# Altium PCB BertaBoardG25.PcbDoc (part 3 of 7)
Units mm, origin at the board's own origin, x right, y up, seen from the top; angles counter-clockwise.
Board outline 160 x 160 mm, 4 copper layers (Top, GND Plane, Power Plane, Bottom), stack 1.344 mm thick; 17 components, 112 nets, 2311 pads, 138 vias.
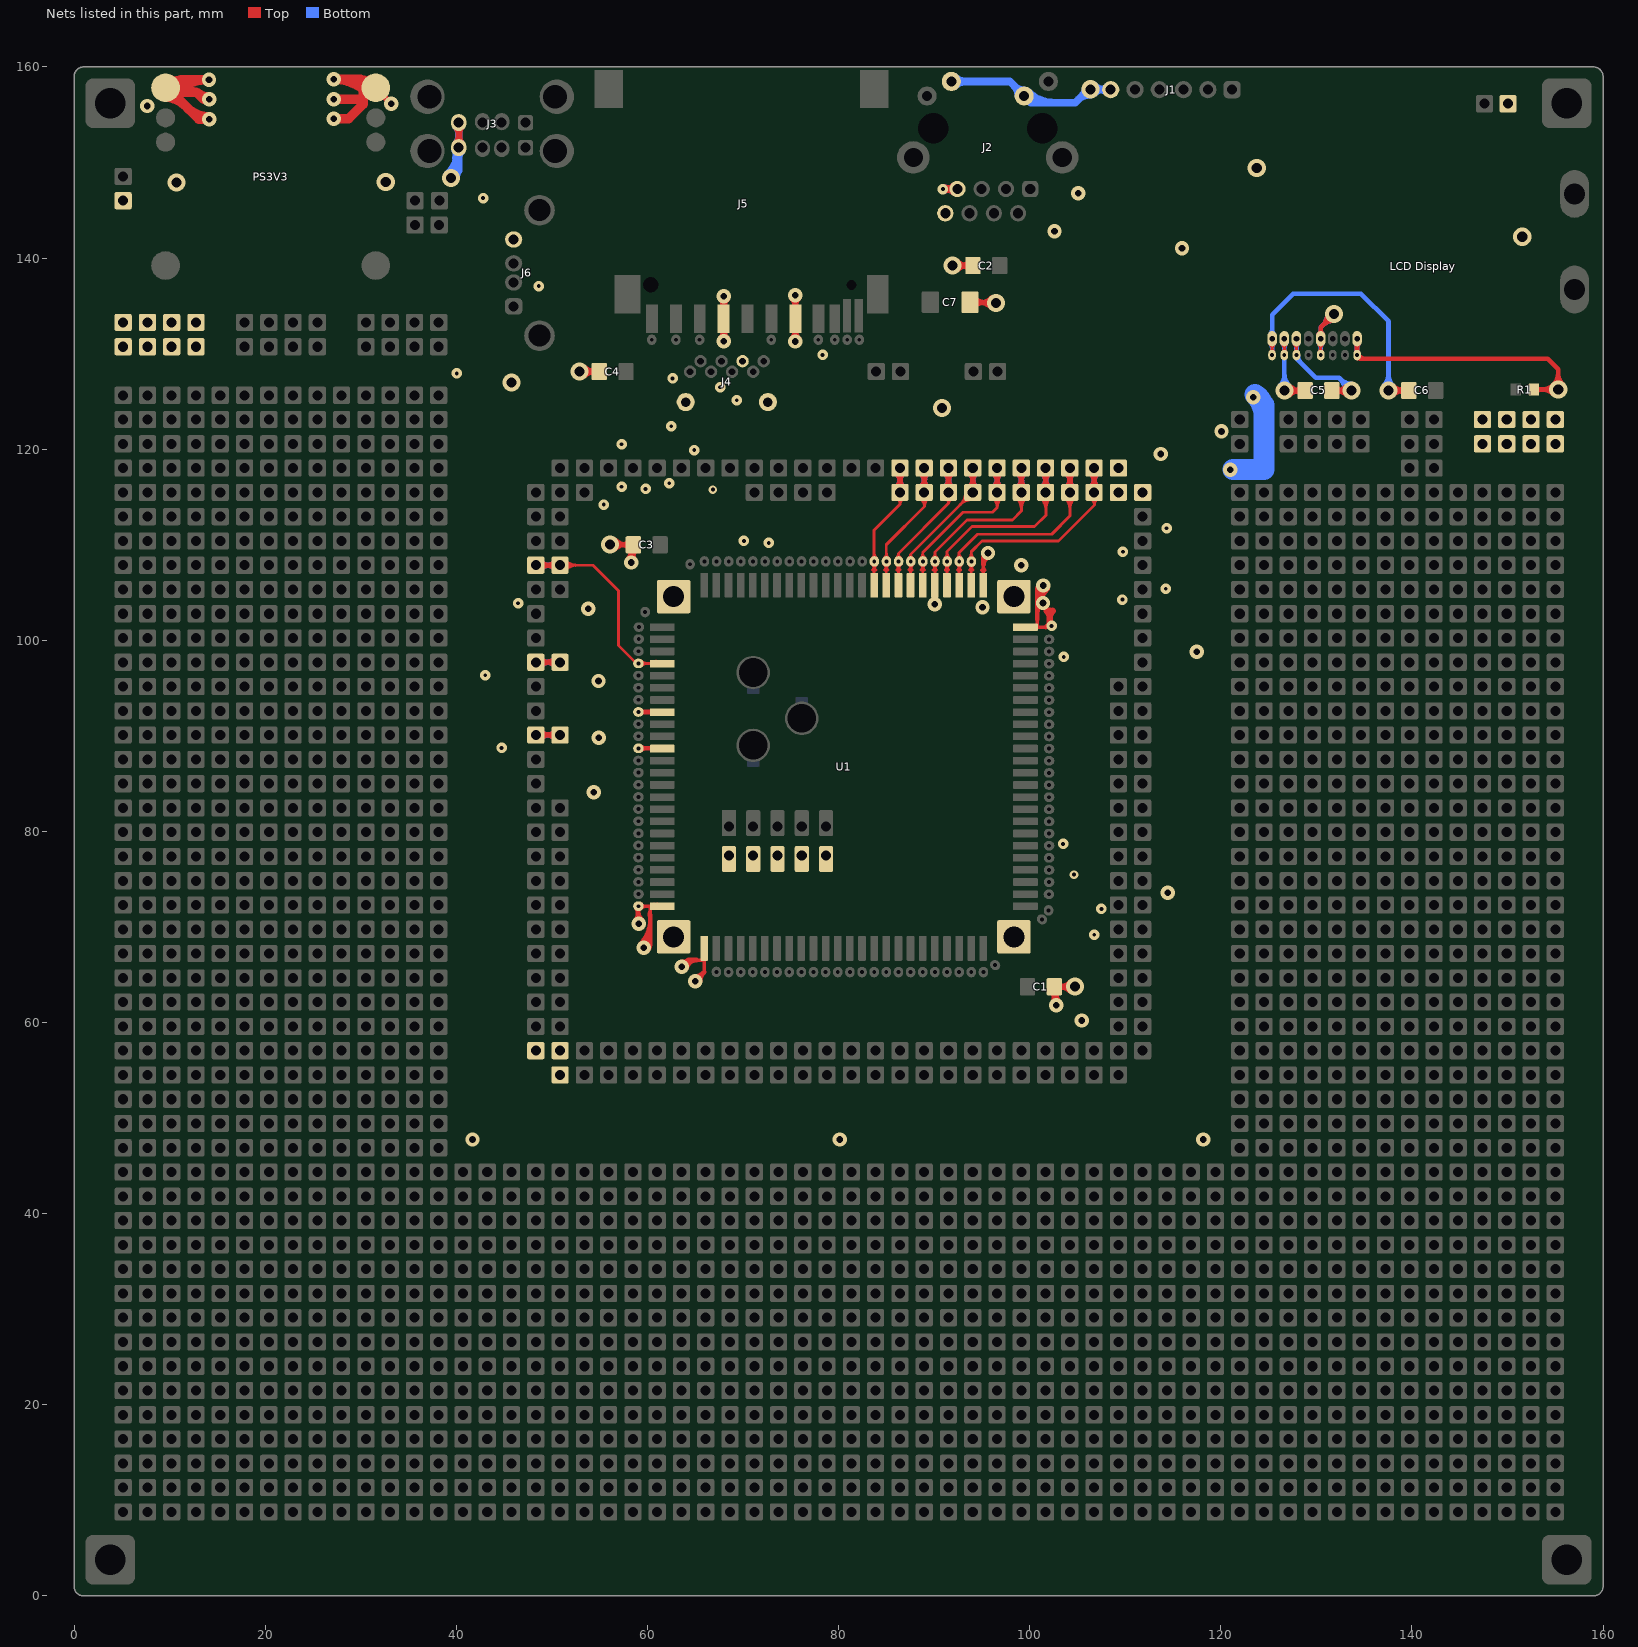
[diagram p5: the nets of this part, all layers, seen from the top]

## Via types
v1: diameter 1.5, hole 0.7, Top to Bottom, tented both sides, 54 vias
v2: diameter 1.1, hole 0.4, Top to Bottom, tented both sides, 49 vias
v3: diameter 1.9, hole 1.05, Top to Bottom, tented both sides, 17 vias
v4: diameter 1.9, hole 1.05, Top to Bottom, 16 vias
v5: diameter 0.9, hole 0.4, Top to Bottom, tented both sides, 2 vias

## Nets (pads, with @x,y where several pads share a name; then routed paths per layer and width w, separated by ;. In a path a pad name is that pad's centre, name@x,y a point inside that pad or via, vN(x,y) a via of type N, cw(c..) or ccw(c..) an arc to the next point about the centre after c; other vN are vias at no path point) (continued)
GND: "LCD Display.5" C1.2 C2.2 C3.2 C4.2 C7.1 J1.6 J2.8 J2.10 J2.11 J3.4 J3.8 J4.6 J4.9 J4.10 J5.3 J5.6 J6.4 pad.0@5.142,130.72 pad.0@5.142,133.26 pad.0@5.142,146 pad.0@7.682,130.72 pad.0@7.682,133.26 pad.0@10.222,130.72 pad.0@10.222,133.26 pad.0@12.762,130.72 pad.0@12.762,133.26 pad.0@48.322,57.06 pad.0@48.322,90.08 pad.0@48.322,97.7 pad.0@50.862,54.52 pad.0@50.862,57.06 pad.0@50.862,90.08 pad.0@50.862,97.7 pad.0@59.06,72.182 pad.0@59.06,88.695 pad.0@59.06,92.502 pad.0@109.282,115.48 pad.0@109.282,118.02 pad.0@111.822,115.48 pad.0@130.454,129.853 pad.0@147.382,120.56 pad.0@147.382,123.1 pad.0@149.922,120.56 pad.0@149.922,123.1 pad.0@150.042,156.15 pad.0@152.462,120.56 pad.0@152.462,123.1 pad.0@155.002,120.56 pad.0@155.002,123.1 PS3V3.1 PS3V3.8 U1.2 U1.10 U1.E1 U1.E14 U1.E17 U1.H1 U1.H2 U1.H3 U1.H4 U1.N24 U1.S24 U1.W1 | length 353.6
  Top w0.3: pad.0@48.331,90.11 pad.0@50.871,90.11 ; pad.0@48.331,97.73 pad.0@50.871,97.73 ; pad.0@48.64,89.761 cw(c49.481,88.92) 49.481,90.11 ; pad.0@48.64,90.398 ccw(c49.335,91.093) 49.335,90.11 ; pad.0@48.64,97.381 cw(c49.481,96.54) 49.481,97.73 ; pad.0@48.64,98.018 ccw(c49.335,98.713) 49.335,97.73 ; pad.0@48.685,90.346 ccw(c49.117,90.663) 49.255,90.145 ; pad.0@48.685,97.966 ccw(c49.117,98.283) 49.255,97.765 ; pad.0@48.852,89.549 cw(c50.205,88.196) pad.0@50.205,90.11 ; pad.0@48.852,90.61 ccw(c50.06,91.817) pad.0@50.06,90.11 ; pad.0@48.852,97.169 cw(c50.205,95.816) pad.0@50.205,97.73 ; pad.0@48.852,98.23 ccw(c50.06,99.437) pad.0@50.06,97.73 ; pad.0@48.927,90.523 ccw(c49.496,90.941) 49.679,90.258 ccw(c49.976,89.15) pad.0@48.976,89.712 ; pad.0@48.927,98.143 ccw(c49.496,98.561) 49.679,97.878 ccw(c49.976,96.77) pad.0@48.976,97.332 ; pad.0@48.961,89.687 cw(c49.453,89.385) 49.602,89.943 cw(c49.859,90.903) pad.0@48.983,90.434 ; pad.0@48.961,97.307 cw(c49.453,97.005) 49.602,97.563 cw(c49.859,98.523) pad.0@48.983,98.054 ; pad.0@48.978,90.11 cw(c48.978,88.196) pad.0@50.331,89.549 ; pad.0@48.978,97.73 cw(c48.978,95.816) pad.0@50.331,97.169 ; pad.0@49.124,90.11 ccw(c49.124,91.817) pad.0@50.331,90.61 ; pad.0@49.124,97.73 ccw(c49.124,99.437) pad.0@50.331,98.23 ; 49.703,90.11 cw(c49.703,88.92) pad.0@50.544,89.761 ; 49.703,97.73 cw(c49.703,96.54) pad.0@50.544,97.381 ; 49.848,90.11 ccw(c49.848,91.093) pad.0@50.544,90.398 ; 49.848,97.73 ccw(c49.848,98.713) pad.0@50.544,98.018 ; 130.206,131.014 cw(c129.609,130.417) 130.454,130.417 cw(c131.299,130.417) 130.701,131.014 ; pad.0@130.277,130.179 ccw(c129.85,130.606) 130.454,130.606 ccw(c131.057,130.606) pad.0@130.631,130.179 ; pad.0@130.454,130.16 130.454,131.562
  Top w0.35: pad.0@59.34,71.952 cw(c59.852,71.44) 59.852,72.165 ; pad.0@59.34,72.412 ccw(c59.937,73.009) 59.937,72.165 ; pad.0@59.427,72.165 U1.E1@61.551,72.165 ; 60.185,71.146 cw(c61.921,71.146) U1.E1@60.694,72.373 ; 60.302,71.256 U1.E1@60.302,72.145 ; U1.E1@60.582,72.093 ccw(c60.582,72.616) U1.E1@61.041,72.365 ; U1.E1@61.2,72.165 ccw(c61.2,72.364) U1.E1@61.375,72.268 ; 65.139,66.54 U1.N24@65.901,66.54 ; U1.N24@65.787,67.211 cw(c65.403,66.827) 65.946,66.827 cw(c66.489,66.826) U1.N24@66.105,67.211 ; 65.946,65.284 U1.N24@65.946,67.77 ; 94.997,107.329 ccw(c94.613,107.713) 95.156,107.713 ccw(c95.699,107.713) 95.315,107.329 ; U1.S24@95.136,105.79 U1.S24@95.156,105.77 95.156,108.01 ; U1.W1@99.551,101.375 101.675,101.375 ; U1.W1@99.728,101.478 ccw(c99.902,101.574) U1.W1@99.902,101.375 ; U1.W1@100.8,101.507 100.8,102.193
  Top w0.4: PS3V3.8@31.579,157.819 PS3V3.8@31.916,157.819
  Top w0.5: v4@52.903,128.122 C4.2@54.959,128.122 ; v4@53.396,127.625 cw(c54.595,126.427) C4.2@54.595,128.122 ; v4@53.396,128.615 ccw(c54.588,129.807) C4.2@54.588,128.122 ; v4@53.533,128.422 ccw(c53.881,128.589) 53.981,128.216 ccw(c54.155,127.569) v4@53.542,127.839 ; v4@53.535,127.824 cw(c53.879,127.663) 53.977,128.029 cw(c54.148,128.669) v4@53.542,128.402 ; C4.2@54.57,127.733 ccw(c53.631,126.794) 53.631,128.122 ccw(c53.631,129.45) C4.2@54.57,128.511 ; v4(56.102,110.04) 56.151,109.99 C3.2@58.302,109.99 ; v4@56.597,109.545 cw(c57.672,108.469) 57.672,109.99 ; v4@56.597,110.535 ccw(c57.911,111.849) C3.2@57.911,109.99 ; v1@57.948,108.493 ccw(c57.095,109.347) 58.302,109.347 ccw(c59.509,109.347) v1@58.655,108.493 ; v1@58.139,108.612 ccw(c57.931,109.219) 58.55,109.053 ccw(c59.18,108.885) v1@58.683,108.463 ; C3.2@58.14,109.501 cw(c57.748,109.11) C3.2@58.302,109.11 ; C3.2@58.14,109.601 ccw(c57.201,108.662) 57.201,109.99 ccw(c57.201,111.318) C3.2@58.14,110.379 ; v1@58.302,108.125 cw(c60.145,108.125) C3.2@58.9,109.485 ; v1(58.302,108.14) C3.2@58.302,109.99 ; C3.2@58.302,109.999 C3.2@58.302,109.99 ; C3.2@58.528,109.99 C3.2@58.302,109.99 ; v1@58.748,70.693 ccw(c58.136,71.305) 59.002,71.305 ; pad.0@58.833,72.005 cw(c58.426,71.599) 59.002,71.599 ; v1@59.002,70.44 pad.0@59.002,71.74 ; 59.002,71.559 cw(c59.633,71.559) pad.0@59.187,72.005 ; pad.0@59.06,88.695 61.531,88.695 U1.E14@61.551,88.675 ; pad.0@59.06,92.502 61.534,92.502 U1.E17@61.551,92.485 ; v1@59.248,68.193 ccw(c56.705,70.737) 60.302,70.737 ; pad.0@59.287,88.518 cw(c59.714,88.091) 59.714,88.695 cw(c59.714,89.298) pad.0@59.287,88.872 ; pad.0@59.287,92.325 cw(c59.714,91.899) 59.714,92.502 cw(c59.714,93.106) pad.0@59.287,92.679 ; pad.0@59.427,72.165 pad.0@59.002,71.74 ; v1@59.447,70.702 cw(c60.435,71.74) pad.0@59.002,71.74 ; v1@59.676,68.334 ccw(c59.786,69.056) 60.302,68.54 ; v1@59.955,67.486 ccw(c59.119,68.322) 60.302,68.322 ; v1@60.096,67.914 cw(c60.818,68.023) 60.302,68.54 ; 60.302,69.53 cw(c57.912,69.53) v1(59.602,67.84) 60.302,68.54 ; 60.302,71.256 60.302,68.54 ; v1@63.676,66.334 ccw(c63.786,67.056) 64.302,66.54 ; v1@64.087,65.718 cw(c65.139,65.455) 65.139,66.54 64.302,66.54 ; v1@64.096,65.914 cw(c64.818,66.023) 64.302,66.54 ; 64.498,66.54 ccw(c64.498,65.615) v1(63.602,65.84) 64.302,66.54 ; v1(65.002,64.34) 65.946,65.284 ; v1@65.002,64.84 ccw(c65.002,66.047) 65.855,65.193 ccw(c66.709,64.34) v1@65.502,64.34 ; v4(91.916,139.213) C2.2@94.058,139.211 ; v4@92.411,138.718 cw(c93.603,137.526) C2.2@93.603,139.211 ; v4@92.411,139.708 ccw(c93.61,140.906) C2.2@93.61,139.211 ; v4@92.538,138.891 cw(c93.246,138.524) 93.04,139.294 cw(c92.929,139.706) v4@92.546,139.519 ; v4@92.538,139.535 ccw(c93.252,139.904) 93.044,139.127 ccw(c92.932,138.708) v4@92.543,138.901 ; C2.2@93.67,138.822 ccw(c92.731,137.883) 92.731,139.211 ccw(c92.731,140.539) C2.2@93.67,139.6 ; C7.1@93.754,135.183 93.901,135.33 96.391,135.33 v4@96.461,135.26 ; C7.1@94.213,134.923 cw(c95.195,133.941) 95.195,135.33 ; C7.1@94.213,135.842 ccw(c95.451,137.079) 95.451,135.33 ; 94.734,135.33 cw(c94.734,133.587) v4@95.966,134.819 ; 94.809,135.33 ccw(c94.809,136.967) v4@95.966,135.809 ; 95.156,107.912 cw(c95.957,107.912) v1@95.764,108.689 ; 95.156,108.01 95.156,108.687 95.643,109.174 ccw(c95.798,108.551) 95.156,108.551 ; 100.801,102.193 100.801,105 ; 100.801,102.803 cw(c104.398,102.803) v1@101.854,105.346 ; v1@100.801,104.01 cw(c103.191,104.01) v1@101.501,105.7 ; 100.801,105.217 cw(c101.983,105.217) v1@101.147,106.053 ; v1@101.006,105.625 cw(c100.284,105.516) 100.801,105 ; v1@101.426,105.205 ccw(c101.317,104.484) 100.801,105 ; v1(101.43,105.734) 101.467,105.734 v1@101.501,105.7 ; 101.675,101.375 v2@102.101,101.8 ; 102.001,103.2 102.101,103.1 ; C1.2@102.185,63.26 cw(c100.698,61.774) v1@102.801,61.774 ; v1@102.388,61.983 ccw(c101.579,62.539) 102.528,62.793 ccw(c103.551,63.067) v1@103.041,62.138 ; v1@102.447,62.053 ccw(c101.593,62.907) 102.801,62.907 ccw(c104.008,62.907) v1@103.154,62.053 ; C1.2@102.574,63.749 C1.2@102.801,63.749 ; v1@102.801,61.7 C1.2@102.801,63.749 ; C1.2@102.801,62.869 cw(c103.354,62.869) C1.2@102.963,63.26 ; C1.2@102.963,63.36 cw(c103.902,62.422) 103.902,63.749 cw(c103.902,65.077) C1.2@102.963,64.138 ; C1.2@103.016,63.749 ccw(c103.016,65.475) v4@104.236,64.255 ; C1.2@103.066,63.749 cw(c103.066,62.095) v4@104.236,63.265 ; v4@104.095,64.052 cw(c103.72,64.225) 103.614,63.826 cw(c103.406,63.051) v4@104.114,63.43 ; v4@104.113,64.087 cw(c103.36,64.486) 103.58,63.663 cw(c103.701,63.213) v4@104.113,63.431 ; v4@104.96,63.161 104.372,63.749 C1.2@102.801,63.749 ; 130.277,132.039 ccw(c129.85,132.466) 130.454,132.466 ccw(c131.057,132.466) 130.631,132.039 ; 130.454,131.562 130.454,132.752 v3(131.861,134.16) v3@132.061,134.16 ; v3@131.161,134.16 cw(c129.471,134.16) 130.666,132.965 cw(c131.861,131.77) v3@131.861,133.46 ; 100.801,105 v1@101.501,105.7
  Top w0.6: PS3V3.8@31.687,157.641 v1(33.186,156.143) v1@33.287,156.041
  Top w0.7: J3.4@39.934,151.971 ccw(c39.103,152.802) 40.278,152.802 ; J3.8@39.934,153.755 cw(c39.103,152.924) 40.278,152.924 ; J3.4@40.278,151.553 J3.8@40.278,154.173 ; 40.278,152.676 ccw(c41.276,152.676) J3.4@40.57,151.971 ; 40.278,153.049 cw(c41.276,153.049) J3.8@40.57,153.755 ; v1@67.718,131.583 ccw(c67.035,132.266) 68.001,132.266 ccw(c68.966,132.266) v1@68.283,131.583 ; v1@67.718,135.717 cw(c67.035,135.034) 68.001,135.034 cw(c68.966,135.034) v1@68.283,135.717 ; J5.3@67.783,132.583 cw(c67.257,132.057) 68.001,132.057 ; J5.3@67.783,134.722 ccw(c67.257,135.248) 68.001,135.248 ; v1(68.001,131.3) v1(68.001,136) ; v1@75.188,135.817 cw(c74.505,135.134) 75.471,135.134 cw(c76.436,135.134) v1@75.753,135.817 ; v1@75.198,131.543 ccw(c74.539,132.201) J5.6@75.471,132.201 ; J5.6@75.283,132.583 cw(c74.829,132.13) 75.471,132.13 ; J5.6@75.283,134.722 ccw(c74.829,135.176) 75.471,135.176 ; v1@75.471,131.34 v1@75.471,136.04 ; 75.471,132.098 cw(c76.157,132.098) J5.6@75.672,132.583 ; J5.6@75.471,132.25 ccw(c76.47,132.25) v1@75.763,131.543 ; 75.471,135.207 ccw(c76.157,135.207) J5.6@75.672,134.722 ; 101.818,103.077 cw(c101.135,102.394) 102.101,102.394 cw(c103.066,102.394) 102.383,103.077 ; v2@102.101,101.8 102.101,103.1
  Top w1: PS3V3.1@9.579,156.819 cw(c9.579,153.962) 11.599,155.982 ; PS3V3.1@9.579,157.819 cw(c11.589,155.809) 11.589,158.651 ; PS3V3.1@9.761,157.82 13.06,154.521 v1(14.143,154.521) ; PS3V3.1@10.206,158.598 ccw(c10.669,159.174) 11.192,158.651 ; PS3V3.1@10.286,157.111 cw(c14.003,153.395) v1@14.003,158.651 ; PS3V3.1@10.326,158.484 ccw(c12.811,160.699) 12.811,157.37 ; PS3V3.1@10.579,157.819 ccw(c12.551,157.819) 11.157,156.424 ; 11.867,155.714 ccw(c14.143,157.99) v1@14.143,154.771 ; v1@14.128,156.87 cw(c14.024,158.583) 12.811,157.37 ; v1(14.133,158.651) 11.192,158.651 ; v1(14.143,156.621) 13.56,156.621 12.811,157.37 ; v1(27.179,156.619) 29.662,156.619 ; v1(27.19,154.588) 28.749,154.588 30.261,156.101 30.261,158.46 30.002,158.719 ; 29.495,158.719 cw(c29.495,155.856) PS3V3.8@31.579,157.819 ; PS3V3.8@30.851,157.133 ccw(c27.179,153.674) 27.179,158.719 30.002,158.719 ; PS3V3.8@31,158.634 cw(c30.551,159.268) 30.002,158.719 ; 11.192,158.651 11.011,158.47 11.011,157.37 12.811,157.37
  Bottom w0.3: pad.0@48.331,90.11 pad.0@50.871,90.11 ; pad.0@48.331,97.73 pad.0@50.871,97.73 ; pad.0@48.64,89.761 cw(c49.481,88.92) 49.481,90.11 ; pad.0@48.64,90.398 ccw(c49.335,91.093) 49.335,90.11 ; pad.0@48.64,97.381 cw(c49.481,96.54) 49.481,97.73 ; pad.0@48.64,98.018 ccw(c49.335,98.713) 49.335,97.73 ; pad.0@48.685,90.346 ccw(c49.117,90.663) 49.255,90.145 ; pad.0@48.685,97.966 ccw(c49.117,98.283) 49.255,97.765 ; pad.0@48.852,89.549 cw(c50.205,88.196) pad.0@50.205,90.11 ; pad.0@48.852,90.61 ccw(c50.06,91.817) pad.0@50.06,90.11 ; pad.0@48.852,97.169 cw(c50.205,95.816) pad.0@50.205,97.73 ; pad.0@48.852,98.23 ccw(c50.06,99.437) pad.0@50.06,97.73 ; pad.0@48.927,90.523 ccw(c49.496,90.941) 49.679,90.258 ccw(c49.976,89.15) pad.0@48.976,89.712 ; pad.0@48.927,98.143 ccw(c49.496,98.561) 49.679,97.878 ccw(c49.976,96.77) pad.0@48.976,97.332 ; pad.0@48.961,89.687 cw(c49.453,89.385) 49.602,89.943 cw(c49.859,90.903) pad.0@48.983,90.434 ; pad.0@48.961,97.307 cw(c49.453,97.005) 49.602,97.563 cw(c49.859,98.523) pad.0@48.983,98.054 ; pad.0@48.978,90.11 cw(c48.978,88.196) pad.0@50.331,89.549 ; pad.0@48.978,97.73 cw(c48.978,95.816) pad.0@50.331,97.169 ; pad.0@49.124,90.11 ccw(c49.124,91.817) pad.0@50.331,90.61 ; pad.0@49.124,97.73 ccw(c49.124,99.437) pad.0@50.331,98.23 ; 49.703,90.11 cw(c49.703,88.92) pad.0@50.544,89.761 ; 49.703,97.73 cw(c49.703,96.54) pad.0@50.544,97.381 ; 49.848,90.11 ccw(c49.848,91.093) pad.0@50.544,90.398 ; 49.848,97.73 ccw(c49.848,98.713) pad.0@50.544,98.018
  Bottom w0.5: 130.277,131.085 cw(c129.85,130.658) 130.454,130.658 cw(c131.057,130.658) 130.631,131.085 ; 130.277,132.039 ccw(c129.85,132.466) 130.454,132.466 ccw(c131.057,132.466) 130.631,132.039 ; pad.0@130.461,130.16 130.454,130.167 130.454,131.562 130.454,132.752 v3(131.861,134.16) v3@132.061,134.16 ; v3@131.161,134.16 cw(c129.471,134.16) 130.666,132.965 cw(c131.861,131.77) v3@131.861,133.46
  Bottom w0.8: v3@39.076,148.752 ccw(c36.331,151.553) J3.4@40.252,151.553 ; v3(39.461,148.36) 40.252,149.151 J3.4@40.252,151.553 ; v3@39.636,148.181 ccw(c38.198,149.648) 40.252,149.648 ; J3.4@39.906,151.253 cw(c39.146,150.814) 39.993,150.587 ; 39.961,150.466 cw(c40.979,150.194) J3.4@40.452,151.106 ; J3.8@40.252,154.173 J3.4@40.252,151.553 ; J2.11@91.804,158.478 97.904,158.478 J2.10@99.424,156.958 100.122,156.26 104.761,156.26 106.111,157.61 108.09,157.61 J1.6@108.48,157.22 ; J2.11@92.228,158.053 cw(c93.253,157.029) 93.253,158.478 cw(c93.253,159.926) J2.11@92.228,158.902 ; J2.10@98.824,156.958 ccw(c97.376,156.958) 98.4,157.982 ccw(c99.424,159.006) J2.10@99.424,157.558 ; J2.10@99.283,156.816 ccw(c100.626,158.16) 100.626,156.26 ; J2.10@99.848,157.382 ccw(c102.558,160.091) 102.558,156.26 ; 105.081,156.579 cw(c106.361,155.299) v3@106.361,157.11 ; 105.564,157.062 ccw(c104.966,157.66) v3@105.811,157.66 ; v3@106.75,157.271 cw(c107.568,156.453) 107.568,157.61 ; v3@106.75,158.049 ccw(c107.81,159.108) J1.6@107.81,157.61 ; 107.369,157.61 ccw(c107.369,158.731) J1.6@108.162,157.938 ; 107.418,157.61 cw(c107.418,156.558) J1.6@108.162,157.302 ; 40.252,150.487 cw(c41.218,150.487) 40.535,151.17 ccw(c41.218,150.487) 40.252,150.487 ; 40.252,150.487 ccw(c39.286,150.487) 39.969,151.17 cw(c39.286,150.487) 40.252,150.487 ; 40.252,152.618 cw(c39.286,152.618) 39.969,151.936 ccw(c39.286,152.618) 40.252,152.618 ; 40.252,152.618 ccw(c41.218,152.618) 40.535,151.936 cw(c41.218,152.618) 40.252,152.618 ; 40.252,153.107 cw(c41.218,153.107) 40.535,153.79 ccw(c41.218,153.107) 40.252,153.107 ; 40.252,153.107 ccw(c39.286,153.107) 39.969,153.79 cw(c39.286,153.107) 40.252,153.107
  Bottom w2.2: v1@121.281,117.86 124.511,117.86 124.511,124.62 ; v1@123.562,125.719 cw(c122.542,124.035) 124.511,124.035 ; v1@123.629,125.667 cw(c121.498,123.537) 124.511,123.537
  other v1: 41.701,47.77 80.125,47.77 118.171,47.77 105.461,60.22 102.765,61.818 59.102,70.34 114.461,73.58 54.4,84.1 54.9,89.8 54.877,95.741 117.481,98.82 53.801,103.3 95.07,103.469 90.052,103.764 101.4,103.9 99.122,107.839 95.646,109.138 121.001,117.85 113.701,119.5 120.071,121.86 123.381,125.42 75.481,131.26 75.471,136.1 115.931,141.02 102.601,142.8 105.073,146.79 7.659,155.914 27.179,158.719
  other v2: 106.751,69.2 107.501,71.9 103.501,78.7 44.74,88.733 43.039,96.353 103.561,98.26 102.3,101.5 46.468,103.872 109.701,104.26 114.241,105.4 109.761,109.26 72.701,110.2 70.101,110.4 114.331,111.73 55.431,114.2 59.801,115.84 57.301,116.07 62.294,116.442 64.901,119.9 57.301,120.51 62.501,122.4 69.355,125.129 67.603,126.475 62.641,127.41 40.041,127.926 78.331,129.86 48.627,137.07 42.809,146.272
  other v3: 90.821,124.31 45.791,126.98 151.541,142.23 10.735,147.906 32.621,147.95 123.761,149.44 106.361,157.66
  other v4: 104.731,63.76 52.901,128.12 96.461,135.314
  other v5: 104.639,75.486 66.851,115.774
JTAGSEL: U1.4
NetC5_1: "LCD Display.2" C5.1 pad.0@126.644,129.853 | length 22.1
  Top w0.3: 126.396,131.014 cw(c125.799,130.417) 126.644,130.417 cw(c127.489,130.417) 126.891,131.014 ; pad.0@126.467,130.179 ccw(c126.04,130.606) 126.644,130.606 ccw(c127.247,130.606) pad.0@126.821,130.179 ; pad.0@126.644,130.16 126.644,131.562
  Top w0.5: v4@126.682,126.116 C5.1@128.822,126.116 ; v4@127.175,125.649 cw(c128.302,124.523) C5.1@128.302,126.116 ; v4@127.175,126.639 ccw(c128.439,127.903) C5.1@128.439,126.116 ; v4@127.293,125.806 cw(c127.717,125.572) 127.843,126.04 cw(c128.068,126.883) v4@127.298,126.473 ; v4@127.306,125.83 cw(c127.958,125.501) 127.769,126.207 cw(c127.671,126.574) v4@127.323,126.423 ; v4@127.429,126.116 ccw(c127.429,127.536) C5.1@128.433,126.532 ; v4@127.56,126.116 cw(c127.56,124.88) C5.1@128.433,125.754
  Bottom w0.5: v4@126.185,126.639 ccw(c125.078,127.746) 126.644,127.746 ; 126.467,131.085 cw(c126.04,130.658) 126.644,130.658 cw(c127.247,130.658) 126.821,131.085 ; v4@126.644,126.16 pad.0@126.644,129.853 126.644,131.562 ; 126.644,127.923 ccw(c128.458,127.923) v4@127.175,126.639
  other v4: 126.68,126.144
NetC5_2: "LCD Display.3" C5.2 pad.0@127.913,129.853 | length 26.3
  Top w0.3: 127.665,131.014 cw(c127.068,130.416) 127.913,130.416 cw(c128.758,130.416) 128.16,131.014 ; pad.0@127.736,130.179 ccw(c127.309,130.606) 127.913,130.606 ccw(c128.516,130.606) pad.0@128.09,130.179 ; pad.0@127.913,130.16 127.913,131.561
  Top w0.5: C5.2@131.622,126.116 v4@133.679,126.116 ; C5.2@131.922,126.116 ccw(c131.922,127.903) v4@133.185,126.639 ; C5.2@132.011,125.754 cw(c132.885,124.88) v4@132.885,126.116 ; C5.2@132.011,126.532 ccw(c133.015,127.536) v4@133.015,126.116 ; C5.2@132.059,126.116 cw(c132.059,124.523) v4@133.185,125.649 ; v4@133.033,126.411 cw(c132.725,126.538) 132.639,126.217 cw(c132.484,125.639) v4@133.036,125.872 ; v4@133.043,126.435 cw(c132.376,126.739) 132.566,126.03 cw(c132.678,125.61) v4@133.063,125.815
  Bottom w0.5: 127.736,131.085 cw(c127.309,130.658) 127.913,130.658 cw(c128.516,130.658) 128.09,131.085 ; 127.913,131.561 pad.0@127.913,129.853 127.913,129.508 129.947,127.474 132.377,127.474 v4@133.741,126.11 ; pad.0@128.063,129.703 ccw(c128.895,129.703) 128.306,129.114 ; 132.467,127.384 cw(c131.227,126.144) v4@132.98,126.144 ; 132.53,127.321 ccw(c133.68,128.471) v4@133.68,126.844
  other v4: 133.68,126.144
NetC6_1: "LCD Display.1" C6.1 pad.0@125.361,129.853 | length 42.9
  Top w0.3: 125.125,131.014 cw(c124.528,130.416) 125.373,130.416 cw(c126.218,130.416) 125.62,131.014 ; pad.0@125.184,130.179 ccw(c124.729,130.634) 125.373,130.634 ; pad.0@125.373,130.16 125.373,131.561 ; 125.373,130.578 ccw(c125.937,130.578) pad.0@125.538,130.179
  Top w0.5: v4(137.537,126.144) C6.1@139.679,126.143 ; v4@138.032,125.649 cw(c139.224,124.458) C6.1@139.224,126.143 ; v4@138.032,126.639 ccw(c139.231,127.838) C6.1@139.231,126.143 ; v4@138.159,125.822 cw(c138.867,125.455) 138.66,126.226 cw(c138.55,126.638) v4@138.167,126.451 ; v4@138.159,126.466 ccw(c138.873,126.836) 138.665,126.059 ccw(c138.553,125.64) v4@138.164,125.833 ; C6.1@139.29,125.754 ccw(c138.352,124.815) 138.352,126.143 ccw(c138.352,127.471) C6.1@139.29,126.532
  Bottom w0.5: 125.196,131.085 cw(c124.769,130.658) 125.373,130.658 cw(c125.976,130.658) 125.55,131.085 ; 125.196,132.038 ccw(c124.769,132.465) 125.373,132.465 ccw(c125.976,132.465) 125.55,132.038 ; pad.0@125.361,130.16 125.373,130.171 125.373,131.561 125.373,134.071 127.561,136.26 134.661,136.26 137.551,133.37 v4@137.551,126.264 ; v4@137.042,126.639 ccw(c135.814,127.868) 137.551,127.868 ; 137.551,127.801 ccw(c139.194,127.801) v4@138.032,126.639
"NetLCD Display_8": "LCD Display.8" pad.0@134.263,129.853 R1.1 | length 38.6
  Top w0.5: 134.086,131.085 cw(c133.659,130.658) 134.263,130.658 cw(c134.866,130.658) 134.44,131.085 ; 134.263,131.561 pad.0@134.263,129.853 134.263,129.789 134.592,129.46 ; pad.0@134.289,129.555 cw(c134.349,129.217) 134.592,129.46 ; pad.0@134.369,129.809 ccw(c135.212,130.651) 135.212,129.46 ; R1.1@152.981,126.031 cw(c153.486,125.527) 153.486,126.24 ; R1.1@152.981,126.455 ccw(c153.501,126.975) 153.501,126.24 ; R1.1@153.251,126.24 155.301,126.24 155.301,128.35 154.191,129.46 134.592,129.46 ; 153.608,126.24 ccw(c153.608,127.946) 154.814,126.739 ccw(c153.638,127.915) 155.301,127.915 ; 153.63,126.24 cw(c153.63,124.566) v4@154.814,125.749 ; 155.301,127.953 ccw(c157.018,127.953) v4@155.804,126.739
  Bottom w0.5: 134.086,131.085 cw(c133.659,130.658) 134.263,130.658 cw(c134.866,130.658) 134.44,131.085 ; pad.0@134.261,130.16 134.263,130.161 134.263,131.561
  other v4: 155.309,126.244
"NO NET 1": J2.7 | length 14.4
  Top w0.5: v2(90.921,147.22) 92.431,147.22 J2.7@92.439,147.228 ; v2@90.972,147.22 ccw(c90.972,148.695) J2.7@92.015,147.652 ; v2@91.01,147.22 cw(c91.01,145.798) J2.7@92.015,146.803 ; v2@91.071,146.96 cw(c91.472,146.265) J2.7@91.68,147.04 ; v2@91.071,147.48 ccw(c91.455,148.146) J2.7@91.654,147.403 ; v2@91.133,147.008 cw(c91.645,146.496) 91.645,147.22 cw(c91.645,147.944) v2@91.133,147.432 ; v2@91.18,147.07 cw(c91.769,146.73) 91.593,147.386 ; v2@91.18,147.37 ccw(c91.739,147.693) 91.572,147.069
  Bottom w0.5: v2(90.921,147.22) J2.7@92.431,147.22 ; v2@90.972,147.22 ccw(c90.972,148.695) J2.7@92.015,147.652 ; v2@91.01,147.22 cw(c91.01,145.798) J2.7@92.015,146.803 ; v2@91.071,146.96 cw(c91.472,146.265) J2.7@91.68,147.04 ; v2@91.071,147.48 ccw(c91.455,148.146) J2.7@91.654,147.403 ; v2@91.133,147.008 cw(c91.645,146.496) 91.645,147.22 cw(c91.645,147.944) v2@91.133,147.432 ; v2@91.18,147.07 cw(c91.769,146.73) 91.593,147.386 ; v2@91.18,147.37 ccw(c91.739,147.693) 91.572,147.069
NRST: pad.0@48.322,107.86 pad.0@50.862,107.86 pad.0@59.06,97.582 U1.E21 | length 57.4
  Top w0.3: pad.0@48.322,107.86 pad.0@50.862,107.86 54.29,107.86 56.961,105.189 56.961,99.46 58.856,97.565 U1.E21@61.551,97.565 ; pad.0@48.64,107.541 cw(c49.408,106.773) 49.408,107.86 cw(c49.408,108.946) pad.0@48.64,108.178 ; pad.0@48.852,107.329 cw(c50.132,106.049) 50.132,107.86 cw(c50.132,109.67) pad.0@48.852,108.39 ; 49.949,107.81 cw(c50.077,107.331) pad.0@50.488,107.608 ; 49.949,107.909 ccw(c50.077,108.388) pad.0@50.488,108.111 ; pad.0@50.204,107.499 ccw(c49.266,106.983) 49.543,108.018 ccw(c49.709,108.636) pad.0@50.24,108.278 ; pad.0@50.204,108.221 cw(c49.266,108.736) 49.543,107.702 cw(c49.709,107.083) pad.0@50.24,107.441 ; pad.0@50.331,107.329 ccw(c49.051,106.049) 49.051,107.86 ccw(c49.051,109.67) pad.0@50.331,108.39 ; pad.0@50.544,107.541 ccw(c49.775,106.773) 49.775,107.86 ccw(c49.775,108.946) pad.0@50.544,108.178 ; pad.0@51.18,107.541 cw(c51.948,106.773) 51.948,107.86 cw(c51.948,108.946) pad.0@51.18,108.178 ; pad.0@51.392,107.329 cw(c52.672,106.049) 52.672,107.86 cw(c52.672,109.67) pad.0@51.392,108.39 ; pad.0@59.357,97.335 cw(c59.913,96.779) 59.913,97.565 ; pad.0@59.357,97.83 ccw(c59.997,98.469) 59.997,97.565 ; U1.E21@60.292,97.565 ccw(c60.292,98.419) U1.E21@60.9,97.819 ; U1.E21@61.01,97.565 ccw(c61.01,97.71) U1.E21@61.114,97.608
  Bottom w0.3: pad.0@48.322,107.86 pad.0@50.862,107.86 ; pad.0@48.64,107.541 cw(c49.408,106.773) 49.408,107.86 cw(c49.408,108.946) pad.0@48.64,108.178 ; pad.0@48.852,107.329 cw(c50.132,106.049) 50.132,107.86 cw(c50.132,109.67) pad.0@48.852,108.39 ; 49.949,107.81 cw(c50.077,107.331) pad.0@50.488,107.608 ; 49.949,107.909 ccw(c50.077,108.388) pad.0@50.488,108.111 ; pad.0@50.204,107.499 ccw(c49.266,106.983) 49.543,108.018 ccw(c49.709,108.636) pad.0@50.24,108.278 ; pad.0@50.204,108.221 cw(c49.266,108.736) 49.543,107.702 cw(c49.709,107.083) pad.0@50.24,107.441 ; pad.0@50.331,107.329 ccw(c49.051,106.049) 49.051,107.86 ccw(c49.051,109.67) pad.0@50.331,108.39 ; pad.0@50.544,107.541 ccw(c49.775,106.773) 49.775,107.86 ccw(c49.775,108.946) pad.0@50.544,108.178
NRST1: U1.6
NTRST: U1.8
PA0: pad.0@93.904,108.236 pad.0@106.742,115.48 pad.0@106.742,118.02 U1.S23 | length 56.2
  Top w0.3: pad.0@93.656,107.938 cw(c93.101,107.383) 93.886,107.383 ; pad.0@93.656,108.533 ccw(c93.101,109.089) 93.886,109.089 ; 93.709,107.347 ccw(c93.283,107.773) 93.886,107.773 ccw(c94.49,107.773) 94.063,107.347 ; U1.S23@93.886,105.77 93.886,109.265 95.021,110.4 103.001,110.4 106.771,114.17 ; 93.886,107.299 cw(c94.791,107.299) pad.0@94.151,107.938 ; 93.886,109.173 ccw(c94.791,109.173) pad.0@94.151,108.533 ; pad.0@106.211,116.01 ccw(c104.86,117.361) pad.0@106.771,117.361 ; pad.0@106.211,117.489 cw(c104.86,116.138) pad.0@106.771,116.138 ; pad.0@106.349,116.118 ccw(c106.045,116.611) 106.604,116.761 ccw(c107.566,117.019) pad.0@107.096,116.141 ; pad.0@106.374,116.134 ccw(c105.813,117.133) 106.92,116.836 ccw(c107.601,116.654) pad.0@107.185,116.085 ; pad.0@106.384,114.82 cw(c106.031,114.17) 106.771,114.17 ; pad.0@106.424,115.798 ccw(c105.584,116.637) 106.771,116.637 ; pad.0@106.424,117.701 cw(c105.584,116.862) 106.771,116.862 ; pad.0@106.771,116.28 cw(c108.481,116.28) pad.0@107.272,117.489 ; 106.771,116.495 ccw(c107.757,116.495) pad.0@107.06,115.798 ; 106.771,117.004 cw(c107.757,117.004) pad.0@107.06,117.701 ; pad.0@106.771,117.219 ccw(c108.481,117.219) pad.0@107.272,116.01 ; pad.0@106.771,118.06 106.771,114.17 ; 106.807,116.413 ccw(c107.323,116.274) pad.0@107.007,115.843 ; pad.0@107.143,114.846 ccw(c107.571,114.17) 106.771,114.17
  Bottom w0.3: pad.0@106.211,116.01 ccw(c104.86,117.361) pad.0@106.771,117.361 ; pad.0@106.211,117.489 cw(c104.86,116.138) pad.0@106.771,116.138 ; pad.0@106.349,116.118 ccw(c106.045,116.611) 106.604,116.761 ccw(c107.566,117.019) pad.0@107.096,116.141 ; pad.0@106.374,116.134 ccw(c105.813,117.133) 106.92,116.836 ccw(c107.601,116.654) pad.0@107.185,116.085 ; pad.0@106.424,115.798 ccw(c105.584,116.637) 106.771,116.637 ; pad.0@106.424,117.701 cw(c105.584,116.862) 106.771,116.862 ; pad.0@106.771,115.52 pad.0@106.771,118.06 ; pad.0@106.771,116.28 cw(c108.481,116.28) pad.0@107.272,117.489 ; 106.771,116.495 ccw(c107.757,116.495) pad.0@107.06,115.798 ; 106.771,117.004 cw(c107.757,117.004) pad.0@107.06,117.701 ; pad.0@106.771,117.219 ccw(c108.481,117.219) pad.0@107.272,116.01 ; 106.807,116.413 ccw(c107.323,116.274) pad.0@107.007,115.843
PA1: pad.0@92.634,108.261 pad.0@104.202,115.48 pad.0@104.202,118.02 U1.S22 | length 58.4
  Top w0.3: pad.0@92.386,107.963 cw(c91.831,107.408) 92.616,107.408 ; pad.0@92.386,108.558 ccw(c91.831,109.114) 92.616,109.114 ; 92.439,107.347 ccw(c92.013,107.773) 92.616,107.773 ccw(c93.22,107.773) 92.793,107.347 ; U1.S22@92.616,105.77 92.616,109.165 ; 92.616,107.324 cw(c93.521,107.324) pad.0@92.881,107.963 ; pad.0@92.874,108.565 cw(c93.442,109.165) 92.616,109.165 ; pad.0@103.671,114.949 cw(c102.32,113.598) 104.231,113.598 ; pad.0@103.671,116.01 ccw(c102.32,117.361) pad.0@104.231,117.361 ; pad.0@103.671,117.489 cw(c102.32,116.138) pad.0@104.231,116.138 ; pad.0@103.809,117.381 cw(c103.505,116.888) 104.064,116.738 cw(c105.026,116.481) pad.0@104.556,117.358 ; pad.0@103.834,117.366 cw(c103.273,116.367) 104.38,116.663 cw(c105.061,116.846) pad.0@104.645,117.414 ; pad.0@103.884,115.161 cw(c103.044,114.322) 104.231,114.322 ; pad.0@103.884,115.798 ccw(c103.044,116.637) 104.231,116.637 ; pad.0@103.884,117.701 cw(c103.044,116.862) 104.231,116.862 ; 104.231,113.74 cw(c105.941,113.74) pad.0@104.732,114.949 ; 104.231,114.464 cw(c105.217,114.464) pad.0@104.52,115.161 ; pad.0@104.231,116.28 cw(c105.941,116.28) pad.0@104.732,117.489 ; 104.231,116.495 ccw(c105.217,116.495) pad.0@104.52,115.798 ; 104.231,117.004 cw(c105.217,117.004) pad.0@104.52,117.701 ; pad.0@104.231,117.219 ccw(c105.941,117.219) pad.0@104.732,116.01 ; pad.0@104.231,118.06 104.231,113.03 102.301,111.1 94.551,111.1 92.616,109.165 ; 104.267,117.086 cw(c104.783,117.225) pad.0@104.467,117.656
  Bottom w0.3: pad.0@103.671,116.01 ccw(c102.32,117.361) pad.0@104.231,117.361 ; pad.0@103.671,117.489 cw(c102.32,116.138) pad.0@104.231,116.138 ; pad.0@103.809,117.381 cw(c103.505,116.888) 104.064,116.738 cw(c105.026,116.481) pad.0@104.556,117.358 ; pad.0@103.834,117.366 cw(c103.273,116.367) 104.38,116.663 cw(c105.061,116.846) pad.0@104.645,117.414 ; pad.0@103.884,115.798 ccw(c103.044,116.637) 104.231,116.637 ; pad.0@103.884,117.701 cw(c103.044,116.862) 104.231,116.862 ; pad.0@104.231,115.52 pad.0@104.231,118.06 ; pad.0@104.231,116.28 cw(c105.941,116.28) pad.0@104.732,117.489 ; 104.231,116.495 ccw(c105.217,116.495) pad.0@104.52,115.798 ; 104.231,117.004 cw(c105.217,117.004) pad.0@104.52,117.701 ; pad.0@104.231,117.219 ccw(c105.941,117.219) pad.0@104.732,116.01 ; 104.267,117.086 cw(c104.783,117.225) pad.0@104.467,117.656
PA2: pad.0@91.364,108.261 pad.0@101.662,115.48 pad.0@101.662,118.02 U1.S21 | length 57.2
  Top w0.3: pad.0@91.116,107.963 cw(c90.561,107.408) 91.346,107.408 ; pad.0@91.116,108.558 ccw(c90.561,109.114) 91.346,109.114 ; 91.169,107.347 ccw(c90.743,107.773) 91.346,107.773 ccw(c91.95,107.773) 91.523,107.347 ; U1.S21@91.346,105.77 91.346,109.295 93.951,111.9 100.501,111.9 101.691,113.09 pad.0@101.691,118.06 ; 91.346,107.324 cw(c92.251,107.324) pad.0@91.611,107.963 ; 91.346,109.198 ccw(c92.251,109.198) pad.0@91.611,108.558 ; pad.0@101.131,114.949 cw(c99.78,113.598) 101.691,113.598 ; pad.0@101.131,116.01 ccw(c99.78,117.361) pad.0@101.691,117.361 ; pad.0@101.131,117.489 cw(c99.78,116.138) pad.0@101.691,116.138 ; pad.0@101.269,117.381 cw(c100.965,116.888) 101.524,116.738 cw(c102.486,116.481) pad.0@102.016,117.358 ; pad.0@101.294,117.366 cw(c100.733,116.367) 101.84,116.663 cw(c102.521,116.846) pad.0@102.105,117.414 ; pad.0@101.344,115.161 cw(c100.504,114.322) 101.691,114.322 ; pad.0@101.344,115.798 ccw(c100.504,116.637) 101.691,116.637 ; pad.0@101.344,117.701 cw(c100.504,116.862) 101.691,116.862 ; 101.691,113.74 cw(c103.401,113.74) pad.0@102.192,114.949 ; 101.691,114.464 cw(c102.677,114.464) pad.0@101.98,115.161 ; pad.0@101.691,116.28 cw(c103.401,116.28) pad.0@102.192,117.489 ; 101.691,116.495 ccw(c102.677,116.495) pad.0@101.98,115.798 ; 101.691,117.004 cw(c102.677,117.004) pad.0@101.98,117.701 ; pad.0@101.691,117.219 ccw(c103.401,117.219) pad.0@102.192,116.01 ; 101.727,117.086 cw(c102.243,117.225) pad.0@101.927,117.656
  Bottom w0.3: pad.0@101.131,116.01 ccw(c99.78,117.361) pad.0@101.691,117.361 ; pad.0@101.131,117.489 cw(c99.78,116.138) pad.0@101.691,116.138 ; pad.0@101.269,117.381 cw(c100.965,116.888) 101.524,116.738 cw(c102.486,116.481) pad.0@102.016,117.358 ; pad.0@101.294,117.366 cw(c100.733,116.367) 101.84,116.663 cw(c102.521,116.846) pad.0@102.105,117.414 ; pad.0@101.344,115.798 ccw(c100.504,116.637) 101.691,116.637 ; pad.0@101.344,117.701 cw(c100.504,116.862) 101.691,116.862 ; pad.0@101.691,115.52 pad.0@101.691,118.06 ; pad.0@101.691,116.28 cw(c103.401,116.28) pad.0@102.192,117.489 ; 101.691,116.495 ccw(c102.677,116.495) pad.0@101.98,115.798 ; 101.691,117.004 cw(c102.677,117.004) pad.0@101.98,117.701 ; pad.0@101.691,117.219 ccw(c103.401,117.219) pad.0@102.192,116.01 ; 101.727,117.086 cw(c102.243,117.225) pad.0@101.927,117.656
PA3: pad.0@90.094,108.261 pad.0@99.122,115.48 pad.0@99.122,118.02 U1.S20 | length 55.6
  Top w0.3: pad.0@89.846,107.963 cw(c89.291,107.408) 90.076,107.408 ; pad.0@89.846,108.558 ccw(c89.291,109.114) 90.076,109.114 ; 89.899,107.347 ccw(c89.473,107.773) 90.076,107.773 ccw(c90.68,107.773) 90.253,107.347 ; U1.S20@90.076,105.77 90.076,109.225 93.451,112.6 98.201,112.6 99.151,113.55 pad.0@99.151,118.06 ; 90.076,107.324 cw(c90.981,107.324) pad.0@90.341,107.963 ; 90.076,109.198 ccw(c90.981,109.198) pad.0@90.341,108.558 ; pad.0@98.591,114.949 cw(c97.24,113.598) 99.151,113.598 ; pad.0@98.591,116.01 ccw(c97.24,117.361) pad.0@99.151,117.361 ; pad.0@98.591,117.489 cw(c97.24,116.138) pad.0@99.151,116.138 ; pad.0@98.729,117.381 cw(c98.425,116.888) 98.984,116.738 cw(c99.946,116.481) pad.0@99.476,117.358 ; pad.0@98.754,117.366 cw(c98.193,116.367) 99.3,116.663 cw(c99.981,116.846) pad.0@99.565,117.414 ; pad.0@98.804,115.161 cw(c97.964,114.322) 99.151,114.322 ; pad.0@98.804,115.798 ccw(c97.964,116.637) 99.151,116.637 ; pad.0@98.804,117.701 cw(c97.964,116.862) 99.151,116.862 ; 99.151,113.74 cw(c100.861,113.74) pad.0@99.652,114.949 ; 99.151,114.464 cw(c100.137,114.464) pad.0@99.44,115.161 ; pad.0@99.151,116.28 cw(c100.861,116.28) pad.0@99.652,117.489 ; 99.151,116.495 ccw(c100.137,116.495) pad.0@99.44,115.798 ; 99.151,117.004 cw(c100.137,117.004) pad.0@99.44,117.701 ; pad.0@99.151,117.219 ccw(c100.861,117.219) pad.0@99.652,116.01 ; 99.187,117.086 cw(c99.703,117.225) pad.0@99.387,117.656
  Bottom w0.3: pad.0@98.591,116.01 ccw(c97.24,117.361) pad.0@99.151,117.361 ; pad.0@98.591,117.489 cw(c97.24,116.138) pad.0@99.151,116.138 ; pad.0@98.729,117.381 cw(c98.425,116.888) 98.984,116.738 cw(c99.946,116.481) pad.0@99.476,117.358 ; pad.0@98.754,117.366 cw(c98.193,116.367) 99.3,116.663 cw(c99.981,116.846) pad.0@99.565,117.414 ; pad.0@98.804,115.798 ccw(c97.964,116.637) 99.151,116.637 ; pad.0@98.804,117.701 cw(c97.964,116.862) 99.151,116.862 ; pad.0@99.151,115.52 pad.0@99.151,118.06 ; pad.0@99.151,116.28 cw(c100.861,116.28) pad.0@99.652,117.489 ; 99.151,116.495 ccw(c100.137,116.495) pad.0@99.44,115.798 ; 99.151,117.004 cw(c100.137,117.004) pad.0@99.44,117.701 ; pad.0@99.151,117.219 ccw(c100.861,117.219) pad.0@99.652,116.01 ; 99.187,117.086 cw(c99.703,117.225) pad.0@99.387,117.656
PA4: pad.0@88.824,108.261 pad.0@96.582,115.48 pad.0@96.582,118.02 U1.S19 | length 53.2
  Top w0.3: pad.0@88.576,107.963 cw(c88.021,107.408) 88.806,107.408 ; pad.0@88.576,108.558 ccw(c88.021,109.114) 88.806,109.114 ; 88.629,107.347 ccw(c88.203,107.773) 88.806,107.773 ccw(c89.41,107.773) 88.983,107.347 ; U1.S19@88.806,105.77 88.806,109.175 ; 88.806,107.324 cw(c89.711,107.324) pad.0@89.071,107.963 ; pad.0@89.066,108.563 cw(c89.655,109.175) 88.806,109.175 ; pad.0@96.051,116.01 ccw(c94.7,117.361) pad.0@96.611,117.361 ; pad.0@96.051,117.489 cw(c94.7,116.138) pad.0@96.611,116.138 ; pad.0@96.129,114.882 cw(c95.391,113.91) 96.611,113.91 ; pad.0@96.189,117.381 cw(c95.885,116.888) 96.444,116.738 cw(c97.406,116.481) pad.0@96.936,117.358 ; pad.0@96.214,117.366 cw(c95.653,116.367) 96.76,116.663 cw(c97.441,116.846) pad.0@97.025,117.414 ; pad.0@96.264,115.798 ccw(c95.424,116.637) 96.611,116.637 ; pad.0@96.264,117.701 cw(c95.424,116.862) 96.611,116.862 ; pad.0@96.31,115.121 cw(c95.85,114.514) 96.611,114.514 ; 96.611,114.564 cw(c97.369,114.564) pad.0@96.875,115.138 ; pad.0@96.611,116.28 cw(c98.321,116.28) pad.0@97.112,117.489 ; 96.611,116.495 ccw(c97.597,116.495) pad.0@96.9,115.798 ; 96.611,117.004 cw(c97.597,117.004) pad.0@96.9,117.701 ; pad.0@96.611,117.219 ccw(c98.321,117.219) pad.0@97.112,116.01 ; pad.0@96.611,118.06 96.611,113.91 ; 96.647,117.086 cw(c97.163,117.225) pad.0@96.847,117.656 ; pad.0@97.071,114.911 ccw(c97.93,113.91) 96.611,113.91 ; 88.806,109.175 93.031,113.4 96.101,113.4 96.611,113.91
  Bottom w0.3: pad.0@96.051,116.01 ccw(c94.7,117.361) pad.0@96.611,117.361 ; pad.0@96.051,117.489 cw(c94.7,116.138) pad.0@96.611,116.138 ; pad.0@96.189,117.381 cw(c95.885,116.888) 96.444,116.738 cw(c97.406,116.481) pad.0@96.936,117.358 ; pad.0@96.214,117.366 cw(c95.653,116.367) 96.76,116.663 cw(c97.441,116.846) pad.0@97.025,117.414 ; pad.0@96.264,115.798 ccw(c95.424,116.637) 96.611,116.637 ; pad.0@96.264,117.701 cw(c95.424,116.862) 96.611,116.862 ; pad.0@96.611,115.52 pad.0@96.611,118.06 ; pad.0@96.611,116.28 cw(c98.321,116.28) pad.0@97.112,117.489 ; 96.611,116.495 ccw(c97.597,116.495) pad.0@96.9,115.798 ; 96.611,117.004 cw(c97.597,117.004) pad.0@96.9,117.701 ; pad.0@96.611,117.219 ccw(c98.321,117.219) pad.0@97.112,116.01 ; 96.647,117.086 cw(c97.163,117.225) pad.0@96.847,117.656
PA5: pad.0@87.554,108.261 pad.0@94.042,115.48 pad.0@94.042,118.02 U1.S18 | length 51.4
  Top w0.3: pad.0@87.306,107.963 cw(c86.751,107.408) 87.536,107.408 ; pad.0@87.337,108.586 ccw(c87.017,108.995) 87.536,108.995 ; 87.359,107.347 ccw(c86.933,107.773) 87.536,107.773 ccw(c88.14,107.773) 87.713,107.347 ; U1.S18@87.536,105.77 87.536,108.995 ; 87.536,107.324 cw(c88.441,107.324) pad.0@87.801,107.963 ; pad.0@87.747,108.603 cw(c88.006,108.995) 87.536,108.995 ; 92.726,114.185 cw(c94.042,112.869) pad.0@94.042,114.73 ; 92.776,114.235 ccw(c91.531,115.48) pad.0@93.292,115.48 ; pad.0@93.238,114.697 cw(c94.042,113.893) pad.0@94.042,115.03 ; pad.0@93.288,114.747 ccw(c92.555,115.48) pad.0@93.592,115.48 ; pad.0@93.511,116.01 ccw(c92.16,117.361) pad.0@94.071,117.361 ; pad.0@93.511,117.489 cw(c92.16,116.138) pad.0@94.071,116.138 ; pad.0@93.649,117.381 cw(c93.345,116.888) 93.904,116.738 cw(c94.866,116.481) pad.0@94.396,117.358 ; pad.0@93.674,117.366 cw(c93.113,116.367) 94.22,116.663 cw(c94.901,116.846) pad.0@94.485,117.414 ; pad.0@93.724,115.798 ccw(c92.884,116.637) 94.071,116.637 ; pad.0@93.724,117.701 cw(c92.884,116.862) 94.071,116.862 ; pad.0@94.071,116.28 cw(c95.781,116.28) pad.0@94.572,117.489 ; 94.071,116.495 ccw(c95.057,116.495) pad.0@94.36,115.798 ; 94.071,117.004 cw(c95.057,117.004) pad.0@94.36,117.701 ; pad.0@94.071,117.219 ccw(c95.781,117.219) pad.0@94.572,116.01 ; pad.0@94.071,118.06 94.071,115.52 94.061,115.52 87.536,108.995 ; 94.107,117.086 cw(c94.623,117.225) pad.0@94.307,117.656
  Bottom w0.3: pad.0@93.511,116.01 ccw(c92.16,117.361) pad.0@94.071,117.361 ; pad.0@93.511,117.489 cw(c92.16,116.138) pad.0@94.071,116.138 ; pad.0@93.649,117.381 cw(c93.345,116.888) 93.904,116.738 cw(c94.866,116.481) pad.0@94.396,117.358 ; pad.0@93.674,117.366 cw(c93.113,116.367) 94.22,116.663 cw(c94.901,116.846) pad.0@94.485,117.414 ; pad.0@93.724,115.798 ccw(c92.884,116.637) 94.071,116.637 ; pad.0@93.724,117.701 cw(c92.884,116.862) 94.071,116.862 ; pad.0@94.071,115.52 pad.0@94.071,118.06 ; pad.0@94.071,116.28 cw(c95.781,116.28) pad.0@94.572,117.489 ; 94.071,116.495 ccw(c95.057,116.495) pad.0@94.36,115.798 ; 94.071,117.004 cw(c95.057,117.004) pad.0@94.36,117.701 ; pad.0@94.071,117.219 ccw(c95.781,117.219) pad.0@94.572,116.01 ; 94.107,117.086 cw(c94.623,117.225) pad.0@94.307,117.656
PA6: pad.0@86.284,108.261 pad.0@91.502,115.48 pad.0@91.502,118.02 U1.S17 | length 48.3
  Top w0.3: pad.0@86.036,107.963 cw(c85.481,107.408) 86.266,107.408 ; pad.0@86.04,108.563 ccw(c85.526,109.095) 86.266,109.095 ; 86.089,107.347 ccw(c85.663,107.773) 86.266,107.773 ccw(c86.87,107.773) 86.443,107.347 ; U1.S17@86.266,105.77 86.266,109.095 ; 86.266,107.324 cw(c87.171,107.324) pad.0@86.531,107.963 ; pad.0@86.507,108.58 cw(c86.936,109.095) 86.266,109.095 ; pad.0@90.971,116.01 ccw(c89.692,117.289) pad.0@91.501,117.289 ; pad.0@90.971,117.489 cw(c89.692,116.21) pad.0@91.501,116.21 ; pad.0@91.082,117.398 cw(c90.724,116.866) 91.343,116.7 cw(c92.379,116.423) pad.0@91.863,117.362 ; pad.0@91.141,117.362 cw(c90.627,116.425) 91.659,116.702 cw(c92.276,116.867) pad.0@91.92,117.397 ; pad.0@91.184,115.798 ccw(c90.417,116.565) 91.501,116.565 ; pad.0@91.184,117.701 cw(c90.417,116.935) 91.501,116.935 ; pad.0@91.241,114.776 cw(c91.086,114.359) 91.531,114.359 ; pad.0@91.25,117.646 cw(c90.973,117.235) 91.452,117.106 ; pad.0@91.501,115.52 pad.0@91.501,118.09 ; pad.0@91.501,116.208 cw(c93.314,116.208) pad.0@92.032,117.489 ; 91.501,116.567 ccw(c92.59,116.567) pad.0@91.82,115.798 ; 91.501,116.932 cw(c92.59,116.932) pad.0@91.82,117.701 ; pad.0@91.501,117.292 ccw(c93.314,117.292) pad.0@92.032,116.01 ; pad.0@91.531,115.49 91.531,114.36 ; 91.551,117.107 cw(c92.029,117.235) pad.0@91.753,117.646 ; pad.0@91.813,114.797 ccw(c92.012,114.359) 91.531,114.359 ; 86.266,109.095 91.531,114.36
  Bottom w0.3: pad.0@90.971,116.01 ccw(c89.62,117.361) pad.0@91.531,117.361 ; pad.0@90.971,117.489 cw(c89.62,116.138) pad.0@91.531,116.138 ; pad.0@91.109,117.381 cw(c90.805,116.888) 91.364,116.738 cw(c92.326,116.481) pad.0@91.856,117.358 ; pad.0@91.134,117.366 cw(c90.573,116.367) 91.68,116.663 cw(c92.361,116.846) pad.0@91.945,117.414 ; pad.0@91.184,115.798 ccw(c90.344,116.637) 91.531,116.637 ; pad.0@91.184,117.701 cw(c90.344,116.862) 91.531,116.862 ; pad.0@91.531,115.52 pad.0@91.531,118.06 ; pad.0@91.531,116.28 cw(c93.241,116.28) pad.0@92.032,117.489 ; 91.531,116.495 ccw(c92.517,116.495) pad.0@91.82,115.798 ; 91.531,117.004 cw(c92.517,117.004) pad.0@91.82,117.701 ; pad.0@91.531,117.219 ccw(c93.241,117.219) pad.0@92.032,116.01 ; 91.567,117.086 cw(c92.083,117.225) pad.0@91.767,117.656
PA7: pad.0@85.014,108.261 pad.0@88.962,115.48 pad.0@88.962,118.02 U1.S16 | length 48.9
  Top w0.3: pad.0@84.766,107.963 cw(c84.211,107.408) 84.996,107.408 ; pad.0@84.766,108.558 ccw(c84.211,109.114) 84.996,109.114 ; 84.819,107.347 ccw(c84.393,107.773) 84.996,107.773 ccw(c85.6,107.773) 85.173,107.347 ; U1.S16@84.996,105.77 84.996,109.995 88.991,113.99 ; 84.996,107.324 cw(c85.901,107.324) pad.0@85.261,107.963 ; 84.996,109.198 ccw(c85.901,109.198) pad.0@85.261,108.558 ; pad.0@88.431,116.01 ccw(c87.08,117.361) pad.0@88.991,117.361 ; pad.0@88.431,117.489 cw(c87.08,116.138) pad.0@88.991,116.138 ; pad.0@88.534,114.863 cw(c87.928,113.99) 88.991,113.99 ; pad.0@88.569,116.118 ccw(c88.265,116.611) 88.824,116.761 ccw(c89.786,117.019) pad.0@89.316,116.141 ; pad.0@88.594,116.134 ccw(c88.033,117.133) 89.14,116.836 ccw(c89.821,116.654) pad.0@89.405,116.085 ; pad.0@88.644,115.798 ccw(c87.804,116.637) 88.991,116.637 ; pad.0@88.644,117.701 cw(c87.804,116.862) 88.991,116.862 ; pad.0@88.705,115.11 cw(c88.326,114.563) 88.991,114.563 ; pad.0@88.991,116.28 cw(c90.701,116.28) pad.0@89.492,117.489 ; 88.991,116.495 ccw(c89.977,116.495) pad.0@89.28,115.798 ; 88.991,117.004 cw(c89.977,117.004) pad.0@89.28,117.701 ; pad.0@88.991,117.219 ccw(c90.701,117.219) pad.0@89.492,116.01 ; pad.0@88.991,118.06 88.991,113.99 ; 89.027,116.413 ccw(c89.543,116.274) pad.0@89.227,115.843 ; pad.0@89.427,114.892 ccw(c90.141,113.99) 88.991,113.99
  Bottom w0.3: pad.0@88.431,116.01 ccw(c87.08,117.361) pad.0@88.991,117.361 ; pad.0@88.431,117.489 cw(c87.08,116.138) pad.0@88.991,116.138 ; pad.0@88.569,116.118 ccw(c88.265,116.611) 88.824,116.761 ccw(c89.786,117.019) pad.0@89.316,116.141 ; pad.0@88.594,116.134 ccw(c88.033,117.133) 89.14,116.836 ccw(c89.821,116.654) pad.0@89.405,116.085 ; pad.0@88.644,115.798 ccw(c87.804,116.637) 88.991,116.637 ; pad.0@88.644,117.701 cw(c87.804,116.862) 88.991,116.862 ; pad.0@88.991,115.52 pad.0@88.991,118.06 ; pad.0@88.991,116.28 cw(c90.701,116.28) pad.0@89.492,117.489 ; 88.991,116.495 ccw(c89.977,116.495) pad.0@89.28,115.798 ; 88.991,117.004 cw(c89.977,117.004) pad.0@89.28,117.701 ; pad.0@88.991,117.219 ccw(c90.701,117.219) pad.0@89.492,116.01 ; 89.027,116.413 ccw(c89.543,116.274) pad.0@89.227,115.843
PA8: pad.0@83.744,108.261 pad.0@86.422,115.48 pad.0@86.422,118.02 U1.S15 | length 47.1
  Top w0.3: pad.0@83.496,107.963 cw(c82.941,107.408) 83.726,107.408 ; pad.0@83.496,108.558 ccw(c82.941,109.114) 83.726,109.114 ; 83.549,107.347 ccw(c83.123,107.773) 83.726,107.773 ccw(c84.33,107.773) 83.903,107.347 ; U1.S15@83.726,105.77 83.726,111.525 86.451,114.25 ; 83.726,107.324 cw(c84.631,107.324) pad.0@83.991,107.963 ; 83.726,109.198 ccw(c84.631,109.198) pad.0@83.991,108.558 ; pad.0@85.891,116.01 ccw(c84.54,117.361) pad.0@86.451,117.361 ; pad.0@85.891,117.489 cw(c84.54,116.138) pad.0@86.451,116.138 ; pad.0@86.029,116.118 ccw(c85.725,116.611) 86.284,116.761 ccw(c87.246,117.019) pad.0@86.776,116.141 ; pad.0@86.054,116.134 ccw(c85.493,117.133) 86.6,116.836 ccw(c87.281,116.654) pad.0@86.865,116.085 ; pad.0@86.102,114.801 cw(c85.842,114.25) 86.451,114.25 ; pad.0@86.104,115.798 ccw(c85.264,116.637) 86.451,116.637 ; pad.0@86.104,117.701 cw(c85.264,116.862) 86.451,116.862 ; pad.0@86.451,116.28 cw(c88.161,116.28) pad.0@86.952,117.489 ; 86.451,116.495 ccw(c87.437,116.495) pad.0@86.74,115.798 ; 86.451,117.004 cw(c87.437,117.004) pad.0@86.74,117.701 ; pad.0@86.451,117.219 ccw(c88.161,117.219) pad.0@86.952,116.01 ; pad.0@86.451,118.06 86.451,114.25 ; 86.487,116.413 ccw(c87.003,116.274) pad.0@86.687,115.843 ; pad.0@86.788,114.825 ccw(c87.11,114.25) 86.451,114.25
  Bottom w0.3: pad.0@85.891,116.01 ccw(c84.54,117.361) pad.0@86.451,117.361 ; pad.0@85.891,117.489 cw(c84.54,116.138) pad.0@86.451,116.138 ; pad.0@86.029,116.118 ccw(c85.725,116.611) 86.284,116.761 ccw(c87.246,117.019) pad.0@86.776,116.141 ; pad.0@86.054,116.134 ccw(c85.493,117.133) 86.6,116.836 ccw(c87.281,116.654) pad.0@86.865,116.085 ; pad.0@86.104,115.798 ccw(c85.264,116.637) 86.451,116.637 ; pad.0@86.104,117.701 cw(c85.264,116.862) 86.451,116.862 ; pad.0@86.451,115.52 pad.0@86.451,118.06 ; pad.0@86.451,116.28 cw(c88.161,116.28) pad.0@86.952,117.489 ; 86.451,116.495 ccw(c87.437,116.495) pad.0@86.74,115.798 ; 86.451,117.004 cw(c87.437,117.004) pad.0@86.74,117.701 ; pad.0@86.451,117.219 ccw(c88.161,117.219) pad.0@86.952,116.01 ; 86.487,116.413 ccw(c87.003,116.274) pad.0@86.687,115.843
